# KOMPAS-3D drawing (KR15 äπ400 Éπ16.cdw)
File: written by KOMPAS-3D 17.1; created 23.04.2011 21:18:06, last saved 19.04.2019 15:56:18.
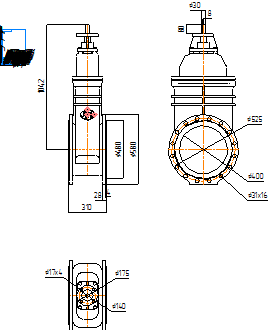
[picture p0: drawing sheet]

Sheet 1: A4, portrait

Title block, sheet 1: name: KR15 Ду400 Ру16; material: Внимание! Данный продукт является объектом авторского права ООО «Торговый Дом АДЛ». / Запрещается изменение, копирование, распространение / (в том числе путем копирования на другие сайты и ресурсы в Интернете) / или любое иное использование информации и объектов без предварительного / согласия правообладателя (ООО «Торговый Дом АДЛ»).; scale: 1:1; sheets: 1; organisation: ООО "Торговый дом АДЛ"; sheet format: A4; stored path: \\adlc.lan\data\АДЛ_ПКД\3D-модели\ADL production\Клиновые задвижки серии KR ГРАНАР\Клиновые задвижки KR15\С голым штоком\KOMPAS 2D\KR15 Ду400 Ру16.cdw

Views: Спереди 7, Проекционный вид 8
Dimensions and other numbers on the sheet: 310; 1042; 480; 580; 28; 4; 140; 175; 17; 1:1; 1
